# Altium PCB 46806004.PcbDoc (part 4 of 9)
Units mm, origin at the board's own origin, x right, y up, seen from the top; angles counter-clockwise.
Board outline 130 x 105 mm, 8 copper layers (Top Layer, P1-GND, L1-Signal, L2-Signal, L3-Signal, L4-Signal, P2-GND, Bottom Layer), stack 1.63 mm thick; 796 components, 496 nets, 2808 pads, 1195 vias.
Unrouted connection lines stored in the file: 1.
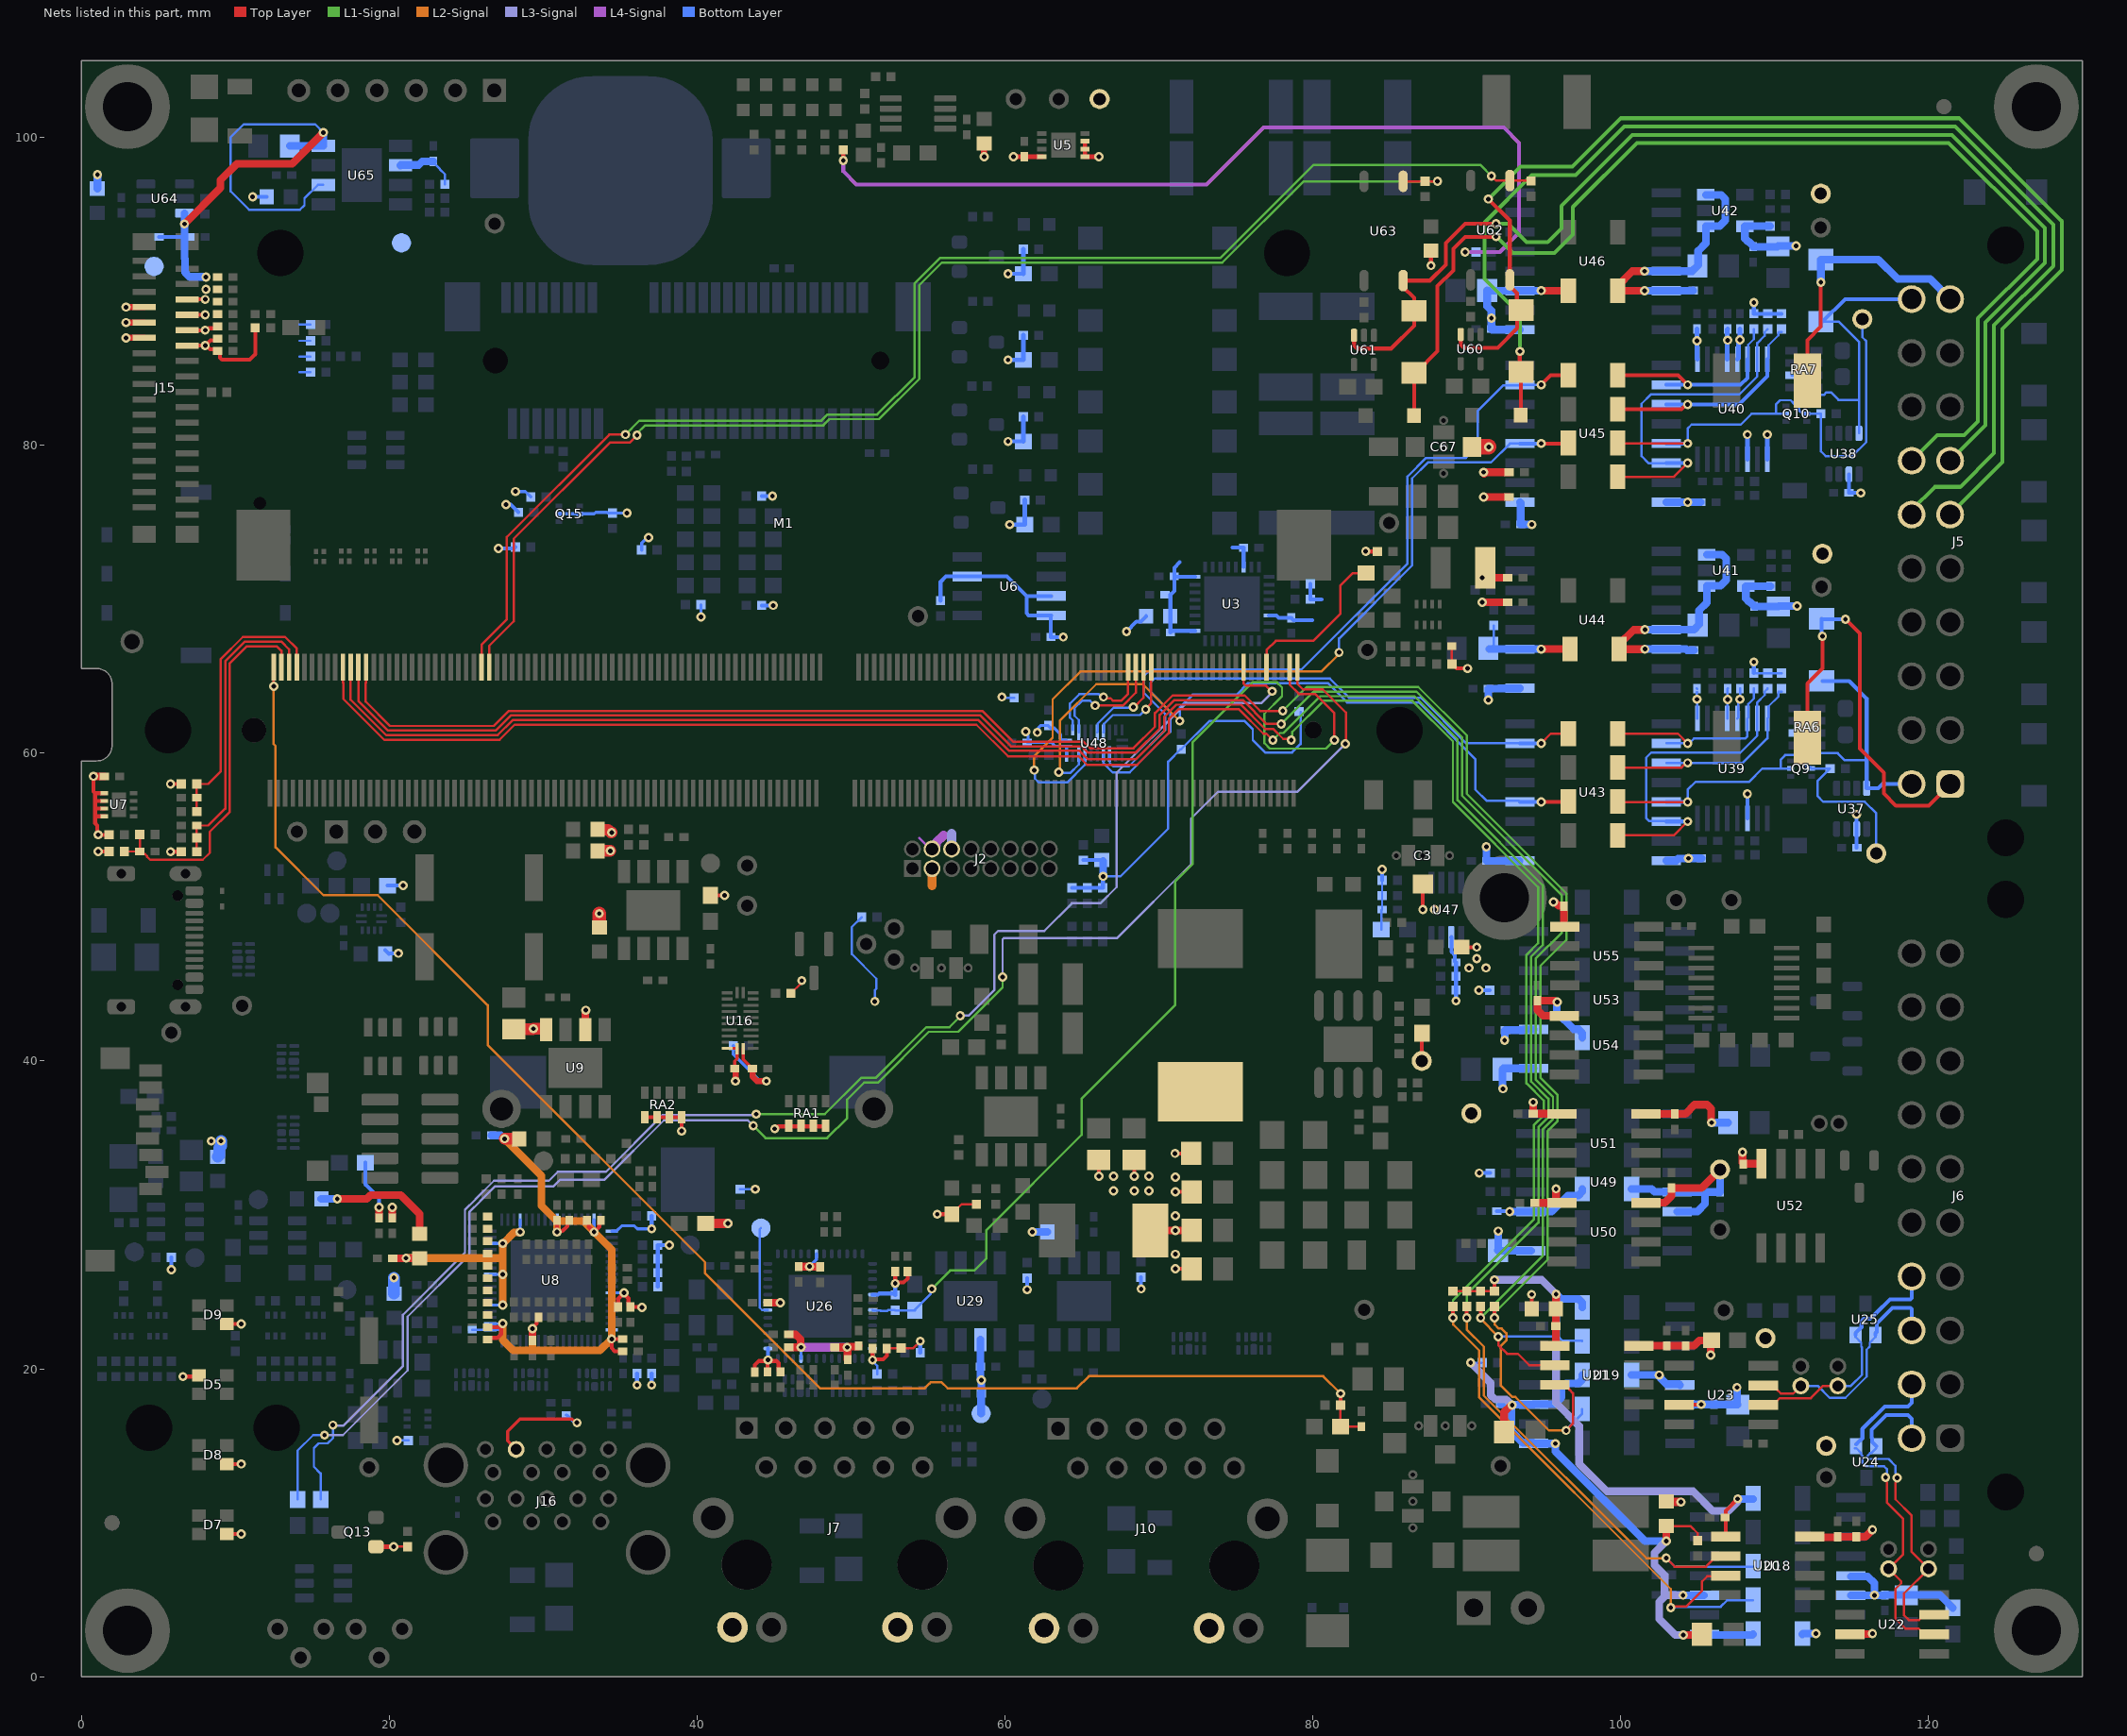
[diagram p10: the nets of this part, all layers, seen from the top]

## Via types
v1: diameter 0.6, hole 0.3, Top Layer to Bottom Layer, tented both sides, 1130 vias
v2: diameter 0.6, hole 0.3, Top Layer to Bottom Layer, 53 vias
v3: diameter 0.3, hole 0.3, Top Layer to Bottom Layer, 12 vias

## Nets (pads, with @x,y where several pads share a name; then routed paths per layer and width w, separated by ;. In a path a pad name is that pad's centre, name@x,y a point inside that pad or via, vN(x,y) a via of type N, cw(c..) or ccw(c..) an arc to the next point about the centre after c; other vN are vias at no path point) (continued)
1V8: C14.2 C16.2 C111.2 C135.2 C137.2 C140.2 C144.2 C147.2 C150.2 C153.2 C157.2 C160.2 C161.2 C162.2 C164.2 C215.2 C216.2 J2.6 L3.1 L4.2 L25.1 L29.1 L32.2 Q15.2 Q15.5 R4.1 R7.2 R56.2 R58.2 R61.2 R85.2 R115.2 R117.1 R120.2 R121.2 R133.1 R140.2 R147.2 R157.2 R183.2 R184.2 R215.1 R220.2 R221.2 R222.1 R224.2 R264.1 R265.1 R267.1 R269.1 R274.2 R275.2 R276.2 RA1.1 RA1.2 RA1.3 RA1.4 U5.1 U5.2 U5.3 U5.8 U7.5 U7.6 U7.7 U7.8 U16.24 U26.13 U26.19 U26.30 U26.41 U26.48 U47.2 U48.24 X2.1 | length 107.4
  Top Layer w0.15: R222.1@46.1,44.4 46.714,45.014 46.714,45.139 v1(46.8,45.225)
  Top Layer w0.156: C135.2@52.325,21.325 52.35,21.35 R221.2@53.25,21.35 54.05,21.35 v1(54.5,21.8) ; v1(52.871,25.547) v1@52.934,25.484
  Top Layer w0.2: U16.24@43,40.8 43,40.1 C111.2@43.6,39.5
  Top Layer w0.25: v1(0.8,58.5) 0.8,57.5 0.9,57.4 ; U7.8@1.5,55.9 0.9,55.9 ; U7.7@1.5,56.4 0.9,56.4 ; U7.6@1.5,56.9 0.9,56.9 ; U7.5@1.5,57.4 0.9,57.4 ; R7.2@1.8,54.7 v1(1.1,54.7) 1.033,54.767 1.033,55.313 0.9,55.446 0.9,55.9 ; v1(5.8,58) R56.2@6.5,58 ; C160.2@43.75,19.8 43.75,20.25 44.015,20.515 44.537,20.515 v1@44.59,20.567 ; C162.2@44.575,19.803 44.59,19.818 v1@44.59,20.567 ; C164.2@45.424,19.803 45.299,19.928 45.299,20.363 45.148,20.515 44.671,20.515 v1(44.604,20.582) v1@44.59,20.567 ; C144.2@51.4,21.325 51.402,21.323 51.402,20.584 v1(51.404,20.582) 51.452,20.629 52.079,20.629 52.325,20.875 C135.2@52.325,21.325 ; v1(51.55,43.875) v1@51.617,43.808 ; v1(52.871,25.547) v1@52.872,25.548 ; C153.2@52.874,26.318 C153.2@52.874,26.318 v1@52.872,25.548 ; C137.2@53.674,26.318 53.674,25.868 53.42,25.614 52.938,25.614 v1@52.872,25.548 ; v1@83.445,73.1 R133.1@84.2,73.1 ; v1(87.675,91.678) L32.2@87.675,92.643 ; L25.1@94.21,23.9 v1(94.21,24.838) ; 0.9,55.9 0.9,56.4 ; 0.9,56.4 0.9,56.9 ; 0.9,56.9 0.9,57.4
  Top Layer w0.3: v1(45.05,35.6) 45.131,35.6 45.281,35.75 47.55,35.75 48.3,35.75 RA1.4@48.35,35.8 ; v1(60.55,98.75) 61.45,98.75 U5.8@62.4,98.75 ; U5.3@65.2,99.75 U5.2@65.2,99.25 U5.1@65.2,98.75 v1(66.1,98.75)
  Top Layer w0.4: C111.2@43.6,39.5 43.6,39 43.9,38.7 v1(44.5,38.7) ; v1(58.65,98.75) L29.1@58.65,99.61
  Top Layer w0.5: v1(0.8,58.5) C16.2@1.5,58.5 ; C161.2@19.35,29.8 v1(19.35,30.5) ; C157.2@20.2,29.8 v1(20.2,30.5) ; C147.2@44.6,24.3 v1(45.4,24.3) ; C150.2@46.6,26.65 v1(47.3,26.65) 47.312,26.638 47.987,26.638 C140.2@48,26.625
  L3-Signal w0.15: 56.535,54.785 56.55,54.8
  L3-Signal w0.6: J2.6@56.535,53.775 56.535,54.785
  Bottom Layer w0.15: R58.2@50.7,49.35 50.05,48.7 50.05,46.95 51.65,45.35 51.65,44.698 51.55,44.598 v1(51.55,43.875) ; v1(59.8,63.65) 59.85,63.6 R274.2@60.6,63.6 ; v1(66.375,52) 67.5,52 70.6,55.1 70.6,59.45 71.4,60.25 R275.2@71.45,60.25 73.3,62.1 75.55,62.1 76.1,61.55 76.1,60.85 76.9,60.05 78.65,60.05 79.2,60.6 R276.2@79.2,62.669
  Bottom Layer w0.156: R220.2@42.8,31.675 v1(43.775,31.675) ; v1(51.404,20.582) 51.404,20.502 51.7,20.206 R267.1@51.7,19.672
  Bottom Layer w0.2: v1(28.2,77) 28.85,77 R264.1@29.2,76.65 ; Q15.5@31.025,75.55 Q15.2@32.375,75.55 33.322,75.55 33.422,75.65 34.15,75.65 34.2,75.6 R269.1@34.5,75.6 v1(35.45,75.6) ; R224.2@36.4,73.2 36.4,73.648 36.752,74 v1(36.85,74) ; v1(40.25,68.85) R85.2@40.25,69.65 ; R215.1@42.35,41 42.35,40.45 44.076,38.724 44.476,38.724 v1(44.5,38.7) ; U26.19@44.6,24.325 44.612,24.312 45.388,24.312 v1(45.4,24.3) ; v1(47.3,26.65) 47.75,27.1 U26.30@47.75,27.475 ; v1(62.1,61.35) 62.186,61.436 62.186,61.661 62.325,61.8 C215.2@62.8,61.8 62.8,61.775 62.95,61.625 63.2,61.625 63.6,61.225 63.6,60.95 63.7,60.85 U48.24@63.975,60.85
  Bottom Layer w0.25: v1(5.85,26.45) R61.2@5.85,27.25 ; R157.2@18.466,33.4 18.466,31.984 19.35,31.1 v1(19.35,30.5) ; R147.2@44.2,69.6 v1(44.95,69.6) ; R140.2@44.2,76.7 v1(44.9,76.7) ; v1@44.6,20.586 U26.13@44.6,21.325 ; v1@51.4,20.586 U26.48@51.4,21.325 ; U26.41@51.4,24.825 51.762,24.825 51.837,24.9 52.672,24.9 52.7,24.872 52.807,24.872 R121.2@52.875,24.803 v1@52.875,25.543 ; R265.1@54.5,21.05 v1(54.5,21.8) ; R120.2@64.35,51.25 R115.2@65.35,51.25 R117.1@66.35,51.25 66.362,51.262 66.362,51.988 v1(66.375,52) ; R4.1@65.1,53.05 66.29,53.05 L3.1@66.3,53.06 L3.1@66.35,53.01 ; v1(67.9,67.9) 68.54,68.54 68.825,68.54 69.16,68.875 L4.2@69.16,68.9 ; U47.2@88.975,48.025 U47.2@89,48.05 89,47.1 89.221,46.879 89.221,46.479 C216.2@89.3,46.4 R183.2@89.3,45.5 R184.2@89.3,44.62 v1@89.3,43.908
  Bottom Layer w0.3: L3.1@66.35,53.01 L3.1@66.375,52.985
  Bottom Layer w0.5: v1(66.375,52) L3.1@66.375,52.985
  other v1: 89.301,43.907 83.437,73.107
1V8_CAN: C119.1 C120.1 L25.2 R90.1 R91.2 R225.1 R226.1 R227.1 R228.1 U20.1 U21.1 | length 40.9
  Top Layer w0.15: R227.1@89.1,25.05 R225.1@90,25.05 R226.1@90.9,25.05 R228.1@91.8,25.05
  Top Layer w0.25: R228.1@91.8,25.05 v1(91.8,25.787) ; U20.1@106.819,9.065 106.819,10.271 106.78,10.31 106.829,10.359 106.829,10.789 v1(107.6,11.56)
  Top Layer w0.5: U21.1@95.72,21.505 95.788,21.573 C120.1@95.788,22.784 95.788,23.9 95.8,23.912 v1(95.8,24.85)
  L3-Signal w0.5: v1(91.8,25.787) 94.863,25.787 v1(95.8,24.85) 95.8,17.8 97.3,16.3 97.3,13.85 99.1,12.05 103.618,12.05 103.62,12.052 104.703,12.052 105.966,10.789 107.005,10.789 107.581,11.364 107.581,11.541 v1(107.6,11.56)
  Bottom Layer w0.5: v1(95.8,24.85) 95.827,24.85 96.127,24.55 97.25,24.55 97.5,24.3 R90.1@97.5,24 ; v1@107.61,11.55 R91.2@108.6,11.55
1V8_SW: C242.2 C247.2 C249.2 J15.23 J15.24 R200.2 R201.2 R203.2 R207.2 R208.2 R210.2 U65.6 X80.1 | length 15.8
  Top Layer w0.25: J15.23@6.881,86.478 v1(8.05,86.478) ; C249.2@8.85,86.928 8.734,86.813 8.384,86.813 v1(8.05,86.478) ; R210.2@11.3,87.628 11.3,85.919 10.934,85.553 9.148,85.553 9.001,85.699 9.001,86.003 8.876,86.128 C247.2@8.85,86.128 8.748,86.23 8.371,86.23 8.123,86.478 v1(8.05,86.478)
  Top Layer w0.4: v1(2.913,86.978) J15.24@4.081,86.978
  Bottom Layer w0.15: 14.175,84.742 R200.2@14.892,84.742 ; 14.175,85.767 R201.2@14.892,85.767 ; 14.175,86.792 R207.2@14.892,86.792 ; 14.175,87.842 R208.2@14.892,87.842 ; C242.2@22.9,98.35 23.3,97.95 23.3,97.925 23.625,97.6 R203.2@23.625,96.95
  Bottom Layer w0.5: U65.6@20.725,98.185 20.752,98.212 21.912,98.212 22.15,98.45 C242.2@22.875,98.45
1V8C: C9.2 C10.2 C11.2 C12.2 C13.2 C15.2 L4.1 R9.2 R10.2 R11.2 U3.1 U3.8 U3.14 U3.22 U6.3 U6.7 U6.8 | length 28.6
  Bottom Layer w0.25: R11.2@55.817,69.911 55.817,71.127 56.171,71.481 U6.3@57.556,71.481 60.131,71.481 61.401,70.211 ; U6.7@63.017,70.211 61.401,70.211 ; v1(63.786,67.546) C15.2@62.986,67.546 62.986,68.911 U6.8@63.017,68.941 61.548,68.941 61.401,69.088 61.401,70.211 ; 71.35,72.4 71,72.05 C9.2@71,71.5 ; U3.1@72.35,67.95 70.85,67.95 C11.2@70.75,67.85 70.75,70.3 71,70.55 C9.2@71,71.5 ; U3.8@72.35,71.45 71.05,71.45 C9.2@71,71.5 ; 74.775,73.35 C13.2@75.5,73.35 U3.14@75.5,72.1 ; U3.22@77.15,68.95 77.637,68.95 77.787,68.8 C10.2@78.6,68.8 78.6,68.765 78.725,68.64 79.956,68.64 ; R10.2@79.838,71 R9.2@79.838,70 80.563,70
2V5: C143.2 C146.2 C149.2 C152.2 C155.2 C165.2 R22.2 R127.2 U26.3 U26.9 U29.6 X52.1 | length 15.4
  Top Layer w0.5: C146.2@45.95,21.4 v1(46.75,21.4) 46.725,21.425 46.725,21.925 46.4,22.25 C143.2@45.95,22.25 ; C155.2@48.95,21.4 v1(49.75,21.4) ; C152.2@49.8,20.6 49.775,20.625 49.775,21.375 v1(49.75,21.4) ; C149.2@50.5,21.5 50.45,21.45 49.8,21.45 v1(49.75,21.4)
  Top Layer w0.6: R22.2@40.55,29.45 v1(42,29.45)
  L4-Signal w0.6: v1(46.75,21.4) v1(49.75,21.4)
  Bottom Layer w0.2: U26.9@46.75,20.675 v1(46.75,21.4) ; U26.3@49.75,20.675 v1(49.75,21.4)
  Bottom Layer w0.5: U29.6@58.4,21.9 58.4,19.36 58.465,19.295 R127.2@58.465,18.45 58.45,18.435 X52.1@58.45,17.1
  other v1: 58.465,19.268
3V2_AIN1: C183.1 C191.2 C194.1 C195.2 C197.2 C199.2 C203.2 R165.1 R168.2 R170.2 R172.2 U37.6 U39.3 U39.9 U39.12 U39.13 U41.5 U43.16 X61.1 | length 20.4
  Bottom Layer w0.15: C197.2@104.95,64.2 C197.2@104.975,64.175 ; U39.9@104.975,62.25 104.962,62.262 104.962,63.488 v1(104.95,63.5) 104.95,63.95 C197.2@104.975,63.975 ; U39.12@106.925,62.25 106.925,64.175 C195.2@106.95,64.2 ; U39.13@107.575,62.25 107.65,62.325 107.65,63.278 107.75,63.378 C199.2@107.75,64.2 ; R172.2@108.65,65.2 R170.2@109.55,65.2 R168.2@110.45,65.2
  Bottom Layer w0.25: U39.3@108.225,55.75 v1(108.225,57.35) ; R172.2@108.65,65.2 v1(108.65,65.928) ; C183.1@115.325,53.85 U37.6@115.325,55.073 v1(115.325,56.023)
  Bottom Layer w0.5: U43.16@102.95,53.018 103.6,53.018 103.731,53.149 104.381,53.149 v1(104.4,53.168) ; v1@104.402,53.166 C203.2@105.242,53.166 ; R165.1@109.747,70.852 U41.5@108.13,70.852 108.13,70.048 108.335,69.843 108.385,69.843 108.66,69.568 C194.1@108.66,69.543 108.66,69.518 110.235,69.518 110.282,69.565 v1(111.46,69.565)
  other v1: 106.946,63.482 107.75,63.5
3V2_AIN2: C184.1 C192.2 C193.1 C196.2 C198.2 C201.2 C204.2 R164.1 R169.2 R171.2 R173.2 U38.6 U40.1 U40.3 U40.9 U40.12 U40.13 U42.5 U45.16 X60.1 | length 21.9
  Bottom Layer w0.25: v1(108.65,89.278) R173.2@108.65,88.55 R171.2@109.55,88.55 R169.2@110.45,88.55 ; U38.6@114.825,78.126 C184.1@114.825,76.921 114.836,76.911 115.589,76.911 v1(115.6,76.9)
  Bottom Layer w0.3: C196.2@104.95,87.55 v1(104.95,86.8) 104.962,86.788 104.962,85.612 U40.9@104.975,85.6 ; U40.12@106.925,85.6 106.925,87.525 C198.2@106.95,87.55 ; U40.13@107.575,85.6 107.65,85.675 107.65,86.628 107.75,86.728 C201.2@107.75,87.55 ; U40.3@108.225,79.1 v1(108.225,80.7) ; U40.1@109.525,79.1 v1(109.525,80.7)
  Bottom Layer w0.5: U45.16@102.969,76.309 v1@104.349,76.309 ; v1(104.35,76.31) 104.355,76.305 105.195,76.305 C204.2@105.2,76.3 ; R164.1@109.7,94.25 109.694,94.243 108.076,94.243 U42.5@108.07,94.237 108.07,93.433 108.275,93.228 108.325,93.228 108.6,92.953 C193.1@108.6,92.903 110.175,92.903 C192.2@110.2,92.928 110.222,92.95 v1(111.4,92.95)
  other v1: 106.946,86.832 107.75,86.85
3V3: C62.2 C63.2 C83.2 C86.2 C88.2 C89.2 C91.2 C114.2 C207.2 C208.2 C209.2 C213.2 C219.1 C220.1 C228.1 C229.1 C251.2 J2.3 J7.11 J7.13 J10.11 J10.13 J15.25 L5.1 L6.1 L11.2 L26.1 L27.1 L28.1 L31.1 L33.1 Q13.1 R12.1 R13.1 R14.2 R15.2 R16.2 R17.1 R18.1 R36.2 R53.2 R98.1 R99.1 R100.1 R101.1 R102.1 R103.1 R104.1 R105.1 R180.2 R181.2 R182.1 R249.2 R263.2 R270.1 R271.1 RA2.1 RA2.2 RA2.3 RA2.4 U8.28 U16.22 U16.23 U43.1 U45.1 U48.22 U48.23 U50.1 U51.1 U54.1 U55.1 X17.1 | length 84
  Top Layer w0.15: v1(20.3,8.45) R263.2@21.2,8.45 ; C114.2@42.45,39.5 C114.2@42.5,39.45 ; U16.23@42.575,40.825 U16.23@42.6,40.8 ; C83.2@89.023,66.95 89.023,65.821 R36.2@89.048,65.796
  Top Layer w0.2: U16.22@41.95,40.825 U16.23@42.575,40.825 ; C114.2@42.45,39.5 42.45,40 42.6,40.15 U16.23@42.6,40.8
  Top Layer w0.25: v1(5.8,53.6) R53.2@6.5,53.6 ; J15.25@6.881,87.478 v1(8.05,87.478) 8.144,87.478 8.269,87.603 8.725,87.603 C251.2@8.85,87.728 ; C63.2@34.873,24.025 34.873,24.556 v1(35.265,24.947) 35.265,24.853 35.548,24.569 35.548,24.15 C62.2@35.673,24.025 ; C62.2@35.679,24.03 35.697,24.012 36.405,24.012 v1(36.417,24) ; RA2.1@36.6,36.35 RA2.2@37.4,36.35 RA2.3@38.2,36.35 RA2.4@39,36.35 v1(39,35.45) ; R36.2@89.051,65.799 89.35,65.5 v1(90.05,65.5)
  Top Layer w0.3: Q13.1@19.15,8.45 v1(20.3,8.45)
  Top Layer w0.4: v1(42.5,38.7) C114.2@42.5,39.45
  Top Layer w0.5: v1(16.63,31.05) 18.554,31.05 18.803,31.3 20.75,31.3 21.983,30.067 L5.1@21.983,28.774 ; v1(91,69.8) C88.2@92.65,69.8 ; v1(91,71.4) C86.2@92.65,71.4 ; v1(91.1,76.65) C89.2@92.75,76.65 ; v1(91.1,78.25) C91.2@92.75,78.25 ; v1(94.322,37.322) C220.1@94.322,36.585 96.175,36.585 U51.1@96.191,36.568 ; C219.1@94.422,30.785 96.184,30.785 U50.1@96.191,30.792 95.992,30.792 95.8,30.985 v1(95.8,31.7) ; v1(95.639,50.339) 95.658,50.32 95.739,50.32 95.96,50.1 C228.1@96.3,50.1 ; v1(95.883,43.825) 95.788,43.825 95.689,43.924 C229.1@94.594,43.924 94.594,43.306 94.966,42.934 U54.1@96.347,42.934 ; C228.1@96.3,50.05 C228.1@96.3,50.1 ; U55.1@96.37,48.734 96.3,48.804 C228.1@96.3,50.1
  Top Layer w0.75: L28.1@33.54,53.654 v1(34.365,53.654) ; L27.1@33.54,55.054 33.575,55.019 34.222,55.019 34.391,54.85 v1(34.45,54.85)
  Top Layer w0.9: L6.1@33.65,48.68 v1(33.65,49.58)
  L2-Signal w0.2: 55.265,51.385 55.3,51.35
  L2-Signal w0.6: 55.265,51.385 J2.3@55.265,52.505
  Bottom Layer w0.15: v1(20.5,15.35) R16.2@21.25,15.35 ; R182.1@84.45,48.545 84.45,49.795 C209.2@84.5,49.845 R181.2@84.5,50.745 R180.2@84.5,51.745
  Bottom Layer w0.2: U8.28@34.459,24.947 v1(35.265,24.947) ; v1(61.35,61.4) 61.35,61.3 61.5,61.15 61.5,60.75 C213.2@61.45,60.7 63.025,60.7 63.275,60.45 U48.23@63.975,60.45 64,60.425 U48.22@64,59.8
  Bottom Layer w0.25: v1(11.135,96.15) L33.1@12.035,96.15 ; v1(27.1,73.3) 28.1,73.3 R270.1@28.2,73.4 ; v1(27.6,76.15) 27.9,76.15 R271.1@28.4,75.65 ; v1(36.1,18.95) R14.2@36.1,19.7 ; v1(37.05,18.95) R15.2@37.05,19.7 ; R17.1@37.45,25.35 R18.1@37.45,26.25 R13.1@37.45,27.15 R12.1@37.45,28.05 v1(38.2,28.05) ; v1(60.2,80.25) R103.1@61.197,80.249 ; v1(60.2,85.55) R104.1@61.197,85.549 ; v1(60.2,91.15) 61.196,91.15 R105.1@61.197,91.149 ; v1(60.3,74.85) R102.1@61.296,74.85 ; R180.2@84.5,51.745 v1(84.5,52.45)
  Bottom Layer w0.3: R103.1@61.197,80.249 R99.1@61.197,81.849 ; R104.1@61.197,85.549 R100.1@61.197,87.149 ; R105.1@61.197,91.149 R101.1@61.197,92.749 ; R102.1@61.297,74.849 R98.1@61.297,76.449
  Bottom Layer w0.5: L31.1@15.59,31.05 v1(16.63,31.05) ; v1(61.775,28.9) 62.75,28.9 L26.1@62.76,28.91 ; v1(91.267,53.917) 91.284,53.901 91.284,53.016 C207.2@91.3,53 U43.1@93.432,53 ; U45.1@93.45,76.308 93.5,76.258 C208.2@93.5,74.853 v1@94.212,74.853 ; v1(95.883,43.825) 95.883,43.798 95.85,43.765 95.85,43.168 96.95,42.068 97.25,42.068 97.5,41.818 R249.2@97.5,41.518
  other v1: 94.213,74.854
5V: C3.1 C61.2 C67.1 C87.1 C92.2 C93.2 C94.2 C95.2 C96.2 C98.2 C99.2 C210.1 C211.1 C212.2 C214.2 C217.2 C218.1 C226.2 C227.1 D5.1 D7.1 D8.1 D9.1 J2.4 L13.2 L14.2 L15.1 L16.1 L24.1 L34.1 L40.1 R39.2 R44.2 R50.2 R51.2 R59.2 R125.2 R126.2 R138.2 R177.2 R179.2 R187.2 R191.2 R211.2 R243.2 R255.1 R261.1 U8.18 U9.2 U9.4 U44.1 U44.3 U46.1 U46.3 U49.1 U49.3 U53.1 U53.3 X18.1 | length 133.2
  Top Layer w0.15: C87.1@56.55,30.05 57.2,30.7 R39.2@58.15,30.7
  Top Layer w0.25: v1(1.1,53.613) R51.2@1.8,53.613 ; v1(6.6,19.5) 7.578,19.5 D5.1@7.648,19.571 ; D7.1@9.45,9.275 v1(10.394,9.275) ; D8.1@9.45,13.825 v1(10.394,13.825) ; D9.1@9.45,22.925 v1(10.394,22.925) ; R138.2@40.865,50.77 v1(41.795,50.77) ; v1(49.502,98.5) R50.2@49.502,99.2 ; v1(55.6,30.05) C87.1@56.55,30.05 ; v1(66.1,32.525) C95.2@66.1,33.575 ; v1(68.4,32.525) C94.2@68.4,33.575 ; v1(71.05,34) C92.2@72.1,34 ; v1(71.075,26.5) C96.2@72.125,26.5 ; v1(71.075,31.5) C99.2@72.125,31.5 ; R44.2@86.875,41.803 R44.2@86.9,41.828 ; X18.1@87.075,40.007 R44.2@87.075,41.775 ; v1(87.15,49.85) C3.1@87.15,51.5 ; C93.2@89.675,47.4 v1(90.65,47.4)
  Top Layer w0.5: U9.2@32.735,42.05 32.75,42.065 32.75,43.285 v1(32.765,43.3) ; L13.2@69.45,29 v1(71.075,29) C98.2@72.125,29 ; v1(94.831,66.759) 96.696,66.759 R255.1@96.7,66.763 ; v1@94.834,90.049 R261.1@96.6,90.049
  Top Layer w0.55: L24.1@102.952,11.352 v1(103.91,11.352)
  Top Layer w0.75: C61.2@28.1,42.075 v1@29.34,42.075 ; v1(29.365,42.1) 30.145,42.1 U9.4@30.195,42.05
  Top Layer w1: C67.1@90.35,79.9 v1(91.425,79.9)
  L4-Signal w0.15: 54.42,54.503 55.148,53.775 J2.4@55.265,53.775
  L4-Signal w0.25: v1(49.502,98.5) 49.502,97.798 50.35,96.95 73.1,96.95 76.8,100.65 92.4,100.65 93.4,99.65 93.4,93.8 92.152,92.552 v1(89.887,92.552)
  L4-Signal w0.6: J2.4@55.265,53.775 55.535,54.045 55.535,54.189 56.011,54.665
  Bottom Layer w0.15: C212.2@91.464,66.758 91.75,67.044 R177.2@91.75,68.3
  Bottom Layer w0.2: U8.18@34.459,28.947 34.761,28.947 35.113,29.3 35.928,29.3 36.128,29.1 v1(37.05,29.1)
  Bottom Layer w0.25: L16.1@19.74,47.2 19.99,46.95 20.04,47 v1(20.6,47) ; R59.2@19.9,51.4 v1(20.9,51.4) ; v1(37.05,29.1) R211.2@37.05,29.95 ; v1(61.45,25.15) R125.2@61.45,25.9 ; R126.2@68.825,25.95 68.838,25.938 68.838,25.212 v1(68.85,25.2) ; v1(89.887,92.552) R179.2@90.6,92.553 ; v1@90.788,44.607 R191.2@91.5,44.607 ; v1@90.81,32.723 R187.2@91.522,32.723 ; C218.1@91.95,30.25 92.758,30.25 v1(92.791,30.217)
  Bottom Layer w0.5: L34.1@1.05,96.68 v1(1.05,97.59) ; v1(91.4,63.45) C210.1@91.4,64.2 ; C212.2@91.464,66.758 U44.3@93.45,66.758 v1(94.831,66.759) ; C210.1@91.522,64.2 92.1,64.2 92.109,64.209 93.441,64.209 U44.1@93.45,64.218 ; v1(91.599,88.266) 91.599,88.751 91.325,89.025 C214.2@91.325,90.053 91.33,90.048 U46.3@93.45,90.048 ; v1@91.6,88.265 C211.1@91.6,87.553 91.645,87.508 U46.1@93.45,87.508 ; C217.2@92.025,27.7 C217.2@92.047,27.678 ; v1(92.05,28.95) 92.047,28.947 C217.2@92.047,27.678 ; v1(92.35,38.2) 92.325,38.225 C226.2@92.325,39.468 92.38,39.523 U53.1@94.35,39.523 ; v1(92.46,41.343) 92.48,41.363 92.48,41.987 C227.1@92.5,42.007 93.644,42.007 93.7,42.063 U53.3@94.35,42.063 ; v1@92.792,30.218 U49.3@94.172,30.218 95.518,30.218 96.57,31.27 97.25,31.27 97.5,31.52 R243.2@97.5,31.7 ; U46.3@93.452,90.05 v1@94.829,90.05 ; U49.1@94.172,27.678 C217.2@92.047,27.678
  Bottom Layer w0.75: L15.1@8.85,33.79 8.88,33.79 8.965,33.875 8.965,34.365 9.082,34.482 v1(9.082,34.8) ; L40.1@20.311,24.89 v1(20.311,25.93)
  other v1: 71.075,27.45 71.075,29.95 67.05,31.575 68.4,31.575 69.35,31.575 71.075,32.45 67.05,32.525 69.35,32.525 90.809,32.721 8.441,34.801 90.787,44.605 90.15,46.05 91.25,46.05 90.65,46.65 87.9,49.85 94.831,90.052
5V_485: C221.1 C222.1 C223.1 C224.2 C225.1 R243.1 U49.13 U49.14 U50.8 U51.8 U52.8 X69.1 | length 24.6
  Top Layer w0.25: C222.1@103.517,36.568 C222.1@103.522,36.563
  Top Layer w0.5: U50.8@101.652,30.792 102.859,30.792 103.288,31.221 103.288,31.738 C221.1@103.3,31.75 105.248,31.75 X69.1@106.448,32.95 ; U51.8@101.652,36.568 C222.1@103.517,36.568 ; C222.1@103.522,36.563 104.205,36.563 104.81,37.168 105.607,37.168 105.881,36.894 105.881,36.019 v1(105.9,36) ; v1(107.913,34.078) 107.913,33.398 107.981,33.33 U52.8@109.145,33.33
  Bottom Layer w0.5: R243.1@100.7,31.7 102,31.7 102.2,31.5 103.66,31.5 U49.13@103.672,31.488 105.474,31.488 ; U49.14@103.672,30.218 103.68,30.225 104.975,30.225 105.474,30.724 105.474,31.488 ; v1(105.9,36) C224.2@106.975,36 ; X69.1@106.448,32.95 C223.1@106.45,31.488 105.474,31.488
5V_AIN1: C200.2 C205.1 R255.2 U41.1 U41.3 U44.13 U44.14 | length 17.8
  Top Layer w0.5: v1(101.569,66.757) 99.906,66.757 R255.2@99.9,66.763 99.9,67.063 100.845,68.008 101.55,68.008 v1(101.569,68.027)
  Bottom Layer w0.5: v1@101.57,66.758 U44.14@102.95,66.758 104.24,66.758 104.307,66.69 C205.1@104.757,66.69 ; v1(101.569,68.027) U44.13@102.949,68.027 ; U44.13@102.95,68.028 104.77,68.028 105.094,68.353 105.094,69.272 105.59,69.767 U41.1@105.59,70.852 105.59,70.877 106.497,70.877 106.86,71.24 106.86,72.64 106.591,72.909 U41.3@105.59,72.909
5V_AIN2: C202.2 C206.1 R261.2 U42.1 U42.3 U46.13 U46.14 | length 17.9
  Top Layer w0.5: v1(101.55,90.046) 99.807,90.046 R261.2@99.8,90.053 99.8,90.353 100.763,91.316 v1(101.55,91.316)
  Bottom Layer w0.5: v1@101.551,90.047 U46.14@102.931,90.047 ; v1@101.551,91.317 U46.13@102.931,91.317 ; U46.14@102.95,90.048 102.952,90.05 104.697,90.05 C206.1@104.7,90.053 ; U46.13@102.95,91.318 104.64,91.318 105.035,91.713 105.035,92.632 105.53,93.127 U42.1@105.53,94.237 106.437,94.237 106.8,94.6 106.8,96 106.531,96.269 U42.3@105.53,96.269
5V_CAN: C115.2 C116.2 C117.1 C118.1 L24.2 R86.2 R87.2 R233.2 R237.1 U18.1 U18.3 U19.1 U19.3 | length 49.3
  Top Layer w0.15: L24.2@102.95,9.77 104.55,9.77 105,9.32 R86.2@105,8.81
  Top Layer w0.25: L24.2@102.95,9.77 L24.2@102.952,9.768
  Top Layer w0.5: C116.2@92.425,15.9 92.425,17.175 92.881,17.631 92.931,17.631 v1(92.95,17.65) ; v1(102.952,8.81) L24.2@102.952,9.768 ; v1(104.069,2.714) 105.271,2.714 C115.2@105.275,2.71
  L3-Signal w0.5: v1(90.25,20.4) 91.55,19.1 91.55,18.3 91.843,18.007 92.566,18.007 92.923,17.65 v1(92.95,17.65) ; v1(102.952,8.81) 102.2,8.058 102.2,7.25 102.85,6.6 102.85,5.2 ; v1@104.042,2.714 103.536,2.714 102.5,3.75 102.5,4.85 102.85,5.2 ; v1(104.05,5.3) 104.031,5.281 102.931,5.281 102.85,5.2
  Bottom Layer w0.15: v1(90.25,20.4) R87.2@91,20.4
  Bottom Layer w0.5: C118.1@92.2,17.7 92.873,17.7 92.923,17.65 v1(92.95,17.65) ; R237.1@97.5,19.6 97.5,19.3 97.25,19.05 96.45,19.05 96.15,18.75 96.15,18.15 95.7,17.7 94.355,17.7 U19.3@94.35,17.695 94.324,17.669 92.969,17.669 v1(92.95,17.65) ; v1(102.952,8.81) 101.59,8.81 95.75,14.65 v1(95.75,15.15) 95.747,15.152 94.353,15.152 94.3,15.205 93.65,15.205 92.903,15.952 92.903,17.576 92.95,17.623 v1(92.95,17.65) ; C117.1@103.3,5.32 103.31,5.31 104.04,5.31 v1(104.05,5.3) 104.052,5.298 105.392,5.298 U18.3@105.395,5.3 ; v1(104.069,2.714) 108.555,2.715 R233.2@108.6,2.76
5V_CAN1: C121.1 C124.2 C125.2 C129.1 R92.2 R233.1 U18.13 U18.14 U20.8 U22.3 X30.1 | length 16.1
  Top Layer w0.5: U20.8@112.28,9.065 114.094,9.065 C129.1@114.1,9.06 ; C129.1@114.1,9.1 115.9,9.1 v1(116.35,9.55) ; U22.3@114.918,2.738 114.96,2.78 116.33,2.78 v1(116.35,2.8)
  Bottom Layer w0.5: R233.1@111.8,2.76 111.84,2.8 v1(112.675,2.8) ; U18.13@114.95,6.525 114.96,6.515 116.041,6.515 116.478,6.078 v1(116.478,5.3) ; U18.14@114.955,5.3 114.958,5.298 116.475,5.298 v1(116.478,5.3) ; C121.1@117.15,5.3 v1(116.478,5.3) ; C121.1@117.15,5.315 118.335,5.315 120.728,5.315 R92.2@121.567,4.476
5V_CAN2: C122.1 C123.2 C126.2 C130.1 R93.2 R237.2 U19.13 U19.14 U21.8 U23.3 X31.1 | length 15.7
  Top Layer w0.25: U23.3@103.8,17.66 103.818,17.678 105.213,17.678 v1(105.231,17.696)
  Top Layer w0.5: U21.8@101.181,21.505 102.995,21.505 C130.1@103,21.5 104.767,21.5 105.117,21.85 105.888,21.85 R93.2@105.9,21.862 105.85,21.812 v1(105.85,20.9)
  Bottom Layer w0.5: R237.2@100.7,19.6 102.497,19.6 v1(102.498,19.599) ; v1@102.5,19.6 102.5,19.57 102.565,19.505 102.565,19.422 102.972,19.015 103.783,19.015 U19.13@103.85,18.948 ; U19.14@103.85,17.695 v1(105.231,17.696) ; v1(105.231,17.696) C126.2@107.579,17.696 ; v1(107.55,18.8) 107.55,17.725 C126.2@107.579,17.696 ; C126.2@107.6,17.675 C126.2@107.579,17.696
+V5_SW: C240.2 C243.2 C244.2 C246.2 C248.2 C250.2 C252.2 J15.26 J15.27 J15.28 J15.29 U64.6 U65.2 U65.4 X81.1 | length 44
  Top Layer w0.25: J15.27@6.881,88.478 v1(8.05,88.478) ; J15.29@6.881,89.478 v1(8.05,89.478)
  Top Layer w0.4: v1(2.913,87.978) J15.26@4.081,87.978 ; v1(2.913,88.978) J15.28@4.081,88.978
  Top Layer w0.5: v1(6.7,94.378) 9.05,96.728 9.05,97.233 10.117,98.3 13.695,98.3 v1(15.72,100.325)
  Bottom Layer w0.15: v1(15.72,100.325) 15.195,100.85 10.55,100.85 9.7,100 9.7,96.5 10.9,95.3 14.2,95.3 14.5,95.6 14.5,96.041 15.373,96.915 U65.2@15.725,96.915
  Bottom Layer w0.25: C244.2@5.05,93.528 6.7,93.528 ; U64.6@6.7,95.073 U64.6@6.705,95.078
  Bottom Layer w0.5: U64.6@6.7,95.073 v1(6.7,94.378) 6.7,93.528 6.7,92.15 6.735,92.115 6.735,91.24 7.027,90.947 8.08,90.947 v1(8.1,90.928) ; C240.2@13.55,99.45 U65.4@15.72,99.45 ; v1(15.72,100.325) U65.4@15.72,99.45 ; U65.4@15.725,99.455 U65.4@15.72,99.45
  other v1: 8.1,90.128
ADC.ADC1: C97.1 M1.2 R48.1 R49.2 | length 102
  Top Layer w0.15: v1(12.5,64.353) M1.2@12.5,65.6 ; R49.2@81.8,17.5 R48.1@81.8,16.25 C97.1@83.15,16.25
  Top Layer w0.25: R49.2@81.8,17.65 v1(81.8,18.4)
  L2-Signal w0.15: v1(12.5,64.353) 12.5,60.592 12.625,60.467 12.625,53.883 15.733,50.775 19.253,50.775 26.4,43.628 26.4,41.05 40.525,26.925 40.525,26.21 47.993,18.742 54.792,18.742 55.1,19.05 55.108,19.05 55.183,19.125 55.892,19.125 56.275,18.742 64.667,18.742 65.45,19.525 80.675,19.525 v1(81.8,18.4) ; v1@81.725,18.325 v1@81.8,18.25
ADC.ADC2: C100.1 M1.4 R51.1 R52.2 | length 24.9
  Top Layer w0.15: R51.1@2.8,53.613 C100.1@3.8,53.613 ; R52.2@3.8,54.713 C100.1@3.8,53.613 ; M1.4@13,65.6 13,66.65 12.7,66.95 10.75,66.95 9.65,65.85 9.65,56.2 8.35,54.9 8.35,53.532 7.893,53.075 4.47,53.075 4.275,53.27 4.275,53.311 4.148,53.438 3.975,53.438 C100.1@3.8,53.613
ADC.ADC3: C101.1 M1.6 R53.1 R54.2 | length 19.6
  Top Layer w0.15: R53.1@7.5,53.6 R54.2@7.5,54.5 C101.1@7.5,55.3 8.25,55.3 9.35,56.4 9.35,65.976 10.624,67.25 12.993,67.25 13.5,66.743 M1.6@13.5,65.6
ADC.ADC4: C103.1 M1.8 R56.1 R57.2 | length 18
  Top Layer w0.15: R57.2@7.5,56.2 C103.1@7.5,57.1 R56.1@7.5,58 8.25,58 9.05,58.8 9.05,66.1 10.5,67.55 13.239,67.55 14,66.789 M1.8@14,65.6
AIN1+: D24.1 J5.2 RA6.2 U37.4 | length 18.1
  Bottom Layer w0.15: RA6.2@111.3,61.3 111.85,61.3 112.1,61.05 112.1,60.3 112.4,60 114.095,60 114.561,59.534 115.975,59.534
  Bottom Layer w0.25: D24.1@113.1,64.685 114.843,64.685 115.975,63.553 115.975,59.534 U37.4@115.975,57.727 116.727,57.727 117,58 J5.2@118.9,58
AIN1-: D24.2 J5.1 PTC5.1 | length 27.3
  Top Layer w0.25: PTC5.1@112.116,61 112.116,64.516 113.1,65.5 v1(113.1,67.6) ; v1(114.6,68.7) 115.531,67.769 115.531,60.29 117.1,58.721 117.1,57.376 117.876,56.6 120,56.6 J5.1@121.4,58
  Bottom Layer w0.25: v1(113.1,67.6) 113.054,67.646 D24.2@113.054,68.733 113.087,68.7 v1(114.6,68.7)
AIN1_DRDY_3V3: R253.1 U43.7 U48.16 | length 39.3
  Top Layer w0.15: v1(94.831,60.639) 95.455,61.263 R253.1@96.6,61.263
  Bottom Layer w0.15: U48.16@66.4,59.95 66.4,59.35 67,58.75 68.1,58.75 70.75,61.4 70.75,62.7 69.45,64 69.45,64.576 69.724,64.85 81.1,64.85 82.35,63.6 87,63.6 89.962,60.638 U43.7@93.45,60.638
  Bottom Layer w0.25: U43.7@93.45,60.638 v1@94.83,60.638
AIN1_DRDY_ISO: R172.1 R253.2 U39.14 U43.10 | length 13.5
  Top Layer w0.15: R253.2@99.8,61.263 103.727,61.263 v1(104.35,60.64)
  Bottom Layer w0.15: U43.10@102.969,60.639 v1@104.349,60.639 ; v1(104.35,60.64) 104.445,60.64 104.755,60.95 108.079,60.95 108.225,61.096 U39.14@108.225,62.25 108.284,62.309 108.284,63.184 108.65,63.55 R172.1@108.65,64.2
AIN1_MODE_3V3: R254.1 U43.4 U48.20 | length 46.5
  Top Layer w0.25: v1(94.831,56.829) 96.566,56.829 R254.1@96.6,56.863
  L2-Signal w0.15: v1(63.491,58.767) 63.564,58.84 63.564,62.114 65.937,64.487 68.963,64.487 v1(71.358,62.092)
  Bottom Layer w0.15: v1(63.491,58.767) 63.544,58.714 64.239,58.714 64.8,59.274 U48.20@64.8,59.95 ; v1(71.358,62.092) 71.358,62.958 72.2,63.8 75.05,63.8 75.8,64.55 80.976,64.55 82.226,63.3 86.876,63.3 90.55,59.626 90.55,57.65 91.3,56.9 93.378,56.9 U43.4@93.45,56.828
  Bottom Layer w0.25: U43.4@93.45,56.828 v1@94.83,56.828
AIN1_MODE_ISO: Q9.2 Q9.5 R175.2 R254.2 U43.13 X62.1 | length 27.3
  Top Layer w0.15: R254.2@99.8,56.863 99.833,56.83 v1(104.35,56.83)
  Bottom Layer w0.15: v1(104.35,56.83) 104.35,57.624 104.876,58.15 108.352,58.15 109.202,59 110.415,59 ; Q9.2@111.05,59 110.415,59 ; X62.1@116.6,53.5 116.6,56.1 115.85,56.85 113.15,56.85 112.776,57.224 112.776,58.176 R175.2@113.6,59 Q9.5@112.4,59 112.325,59.075 112.15,59.075 112.1,59.125 112.082,59.125 111.725,59.482 111.725,59.518 111.368,59.875 110.684,59.875 110.4,59.591 110.4,59.015 110.415,59
  Bottom Layer w0.25: U43.13@102.969,56.829 v1@104.349,56.829
AIN1_SCL_ISO: R168.1 R251.2 U39.16 U43.11 | length 15.4
  Top Layer w0.15: R251.2@99.8,59.063 103.948,59.063 104.255,59.37 v1(104.35,59.37)
  Bottom Layer w0.15: U43.11@102.969,59.369 v1@104.349,59.369 ; v1(104.35,59.37) 107.927,59.37 109.525,60.968 U39.16@109.525,62.25 109.6,62.325 109.6,63.039 110.241,63.68 110.241,63.975 110.266,64 R168.1@110.45,64
AIN1_SDA_ISO: R170.1 R252.2 U39.15 U43.14 | length 22.8
  Top Layer w0.15: R252.2@99.8,54.663 103.453,54.663 v1(104.35,55.56)
  Bottom Layer w0.15: U43.14@102.95,55.558 102.921,55.587 101.863,55.587 101.65,55.8 101.65,59.7 101.989,60.039 107.774,60.039 108.875,61.141 U39.15@108.875,62.25 108.875,63.296 109.355,63.776 109.355,64.005 R170.1@109.55,64.2
  Bottom Layer w0.25: U43.14@102.969,55.559 v1@104.349,55.559
AIN2+: D25.1 J5.20 RA7.2 U38.4 | length 21.2
  Bottom Layer w0.15: RA7.2@111.1,84.55 111.8,84.55 111.9,84.45 111.9,83.42 112.086,83.234 112.21,83.234 112.251,83.275 113.193,83.275 113.359,83.44 113.66,83.44 114.15,82.95 115.475,82.95 ; D25.1@113,88.038 113.12,88.038 114.162,88.038 115.475,86.725 115.475,82.95 ; U38.4@115.475,80.78 115.475,82.95
  Bottom Layer w0.25: D25.1@113.12,88.038 114.582,89.5 J5.20@118.9,89.5
AIN2-: D25.2 J5.19 PTC6.1 | length 17.7
  Top Layer w0.25: PTC6.1@112.116,84.2 112.116,86.816 113,87.7 v1(113,90.6)
  Bottom Layer w0.5: v1(113,90.6) D25.2@113,92.068 116.732,92.068 118,90.8 120.1,90.8 J5.19@121.4,89.5
AIN2_DRDY_3V3: R259.1 U45.7 U48.15 | length 49.7
  Top Layer w0.25: v1(94.831,83.929) 95.455,84.553 R259.1@96.6,84.553
  Bottom Layer w0.15: U48.15@66.8,60 66.8,59.55 66.809,59.541 66.809,59.365 67.024,59.15 68.05,59.15 70.4,61.5 70.4,62.55 69,63.95 69,64.974 69.476,65.45 79.276,65.45 86.15,72.324 86.15,77.974 87.36,79.184 89.934,79.184 90.7,79.95 90.7,82.228 92.358,83.886 93.408,83.886 U45.7@93.45,83.928 93.451,83.929 v1(94.831,83.929)
AIN2_DRDY_ISO: R173.1 R259.2 U40.14 U45.10 | length 13.6
  Top Layer w0.25: R259.2@99.8,84.553 103.727,84.553 v1(104.35,83.93)
  Bottom Layer w0.15: U40.14@108.225,85.6 108.284,85.659 108.284,86.534 108.65,86.9 R173.1@108.65,87.55
  Bottom Layer w0.25: U45.10@102.969,83.929 v1@104.349,83.929 ; v1(104.35,83.93) 107.78,83.93 108.225,84.375 U40.14@108.225,85.6
AIN2_MODE_3V3: R260.1 U45.4 U48.19 | length 54.5
  Top Layer w0.25: v1(94.831,80.119) 96.566,80.119 R260.1@96.6,80.153
  L2-Signal w0.15: v1(61.9,58.9) 61.9,59.8 63.1,61 63.1,63.5 64.9,65.3 80.55,65.3 81.7,66.45 v1(81.7,66.544)
  Bottom Layer w0.15: v1(61.9,58.9) 61.95,58.85 61.95,58.35 62.2,58.1 64.05,58.1 65.2,59.25 U48.19@65.2,59.95 ; v1(81.7,66.544) 81.7,67.45 86.45,72.2 86.45,77.85 87.484,78.884 91.566,78.884 92.8,80.118 U45.4@93.45,80.118
  Bottom Layer w0.25: U45.4@93.45,80.118 v1(94.831,80.119)
AIN2_MODE_ISO: Q10.2 Q10.5 R174.2 R260.2 U45.13 X63.1 | length 31.8
  Top Layer w0.15: R260.2@99.8,80.153 99.833,80.12 v1(104.35,80.12)
  Bottom Layer w0.15: v1(104.35,80.12) 104.35,81.097 104.603,81.35 107.8,81.35 108.503,82.053 110.078,82.053 ; Q10.2@110.725,82.053 110.078,82.053 ; X63.1@115.7,88.2 115.7,87.018 115.958,86.761 115.958,80.214 115.048,79.305 113.308,79.305 113,79.613 R174.2@113,82.053 Q10.5@112.075,82.053 111.792,82.053 111.597,82.248 111.597,82.356 111.175,82.778 111.175,82.796 111.043,82.928 110.345,82.928 110.078,82.661 110.078,82.053
  Bottom Layer w0.25: U45.13@102.969,80.119 v1@104.349,80.119
AIN2_SCL_ISO: R169.1 R257.2 U40.16 U45.11 | length 15.3
  Top Layer w0.25: R257.2@99.8,82.353 103.948,82.353 104.255,82.66 v1(104.35,82.66)
  Bottom Layer w0.15: U40.16@109.525,85.6 109.6,85.675 109.6,86.5 110.241,87.141 110.241,87.325 110.266,87.35 R169.1@110.45,87.35
  Bottom Layer w0.25: U45.11@102.969,82.659 v1@104.349,82.659 ; v1(104.35,82.66) 107.687,82.66 109.525,84.498 U40.16@109.525,85.6
AIN2_SDA_ISO: R171.1 R258.2 U40.15 U45.14 | length 23.1
  Top Layer w0.15: R258.2@99.8,77.953 103.453,77.953 v1(104.35,78.85)
  Bottom Layer w0.15: U45.14@102.95,78.848 101.802,78.848 101.35,79.3 101.35,82.7 101.95,83.3 107.7,83.3 108.875,84.475 U40.15@108.875,85.6 108.875,86.646 109.355,87.126 109.355,87.355 R171.1@109.55,87.55
  Bottom Layer w0.25: U45.14@102.969,78.849 v1@104.349,78.849
AIN_CTRL.AIN1_DRDY: M1.220 U48.6 | length 6.3
  Top Layer w0.15: v1(68.35,63) 68.4,63 69,63.6 M1.220@69,65.6
  Bottom Layer w0.15: U48.6@66,61.35 66.025,61.375 66.025,61.919 67.056,62.95 68.3,62.95 v1(68.35,63)
AIN_CTRL.AIN1_MODE: M1.216 U48.2 | length 7.9
  Top Layer w0.15: v1(66.4,63.65) 66.486,63.564 66.869,63.564 67.033,63.4 67.542,63.4 68,63.858 M1.216@68,65.6
  Bottom Layer w0.15: U48.2@64.4,61.5 64.4,62.133 64.225,62.308 64.225,63.225 64.831,63.831 66.097,63.831 66.278,63.65 v1(66.4,63.65)
AIN_CTRL.AIN2_DRDY: M1.222 U48.7 | length 6.6
  Top Layer w0.15: v1(69.15,62.85) 69.15,62.892 69.5,63.242 M1.222@69.5,65.6
  Bottom Layer w0.15: U48.7@66.4,61.35 66.425,61.375 66.425,61.895 67.005,62.475 68.775,62.475 v1(69.15,62.85)
AIN_CTRL.AIN2_MODE: M1.218 U48.3 | length 8
  Top Layer w0.15: v1(65.85,63.1) 67.667,63.1 68.5,63.933 M1.218@68.5,65.6
  Bottom Layer w0.15: U48.3@64.8,61.35 64.8,62.158 64.525,62.433 64.525,62.925 65,63.4 65.537,63.4 65.837,63.1 v1(65.85,63.1)
AVDD12: C39.2 C43.2 C46.2 C49.1 C51.2 C52.2 C54.1 C55.1 C56.2 C57.2 C59.1 C60.1 L7.2 U8.10 U8.16 U8.34 U8.46 U8.52 U8.53 | length 45.8
  Top Layer w0.25: C49.1@26.4,21.9 26.515,22.015 27.021,22.015 27.284,22.279 27.284,22.766 27.37,22.853 v1(27.37,22.947) ; C46.2@26.4,22.7 27.123,22.7 v1@27.237,22.814 ; v1(29.311,22.606) 29.311,22.701 29.575,22.964 29.575,23.225 C54.1@29.7,23.35 ; C56.2@30.9,29.65 30.911,29.639 v1(30.911,28.889) 30.978,28.956 31.256,28.956 31.575,29.275 31.575,29.525 C60.1@31.7,29.65 ; C57.2@32.85,29.65 32.962,29.538 32.962,29.238 v1(33.311,28.889) 33.649,29.226 33.649,29.549 C52.2@33.75,29.65 ; C59.1@35.173,21.15 35.168,21.155 34.645,21.155 34.45,21.35 v1(34.45,21.95) C55.1@35.173,21.95
  Top Layer w0.5: C51.2@29.311,21.85 v1(29.311,22.606)
  Top Layer w0.75: v1(27.5,34.95) L7.2@28.453,34.95
  L2-Signal w0.5: v1(27.37,22.947) 27.37,21.88 28.05,21.2 29.315,21.2 ; v1(27.5,34.95) 29.9,32.55 29.9,30.6 30.911,29.589 ; v1(29.311,22.606) 29.311,21.203 29.315,21.2 ; v1(30.911,28.889) 30.911,29.589 ; v1(33.311,28.889) 34.45,27.75 v1(34.45,21.95) 33.7,21.2 29.315,21.2 ; v1@33.358,28.869 32.627,29.6 30.923,29.6 30.911,29.589
  Bottom Layer w0.15: C43.2@25.4,22.547 U8.52@26.564,22.547 ; U8.53@26.564,22.947 v1(27.37,22.947) ; 27.176,22.547 27.287,22.658 ; U8.34@34.45,22.539 U8.34@34.459,22.547
  Bottom Layer w0.2: U8.52@26.564,22.547 27.176,22.547 ; U8.46@29.311,21.8 v1(29.311,22.606) ; v1(30.911,28.889) U8.10@30.911,29.695 ; v1(33.311,28.889) U8.16@33.311,29.695 ; v1(34.45,21.95) U8.34@34.45,22.539
  Bottom Layer w0.5: C39.2@26.65,35.166 27.257,35.166 27.473,34.95 v1(27.5,34.95)
AVDD33: C21.2 C26.2 C30.2 C33.2 C36.2 C40.2 C44.2 C47.2 C50.2 C53.2 L5.2 U8.4 U8.56 U8.61 U8.66 | length 16.7
  Top Layer w0.5: C21.2@20.231,27.181 21.081,27.181 v1(21.1,27.2) 21.103,27.197 21.98,27.197 L5.2@21.983,27.194
  L2-Signal w0.5: v1(21.1,27.2) 27.317,27.2 27.37,27.147 ; v1(27.37,24.147) v1(27.37,26.147) 27.37,27.147 ; v1(28.511,28.889) 28.492,28.869 28.119,28.869 27.397,28.147 v1(27.37,28.147) 27.37,27.147
  Bottom Layer w0.2: U8.56@26.564,24.147 v1(27.37,24.147) ; U8.61@26.564,26.147 v1(27.37,26.147) ; U8.66@26.564,28.147 v1(27.37,28.147) ; v1(28.511,28.889) U8.4@28.511,29.695
CAN1_H: J6.2 J19.2 U22.7 U24.2 | length 21.6
  Top Layer w0.15: 117.85,12.62 117.85,11.53 118.9,10.48 118.9,8.115 J19.2@120,7.015 118.4,5.415 118.4,4 118.715,3.685 119.381,3.685 119.741,4.045 U22.7@120.161,4.045
  Bottom Layer w0.15: U24.2@116.6,14.975 116.6,14.85 116.275,14.525 116.199,14.525 116.036,14.362 116.036,14.238 116.124,14.15 117.403,14.15 117.85,13.703 117.85,13.245 117.864,13.232 117.864,13.019 v1(117.95,12.933)
  Bottom Layer w0.25: U24.2@116.6,14.975 116.325,15.25 116.325,15.496 116.3,15.521 116.3,16.05 117.25,17 118.65,17 118.9,16.75 J6.2@118.9,15.5
CAN1_L: J6.4 J18.2 U22.6 U24.1 | length 22.7
  Top Layer w0.15: 117.3,12.637 117.3,11.302 118.35,10.252 118.35,7.965 J18.2@117.4,7.015 118.215,6.2 118.215,6.075 117.85,5.71 117.85,3.772 118.487,3.135 119.35,3.135 119.71,2.775 U22.6@120.161,2.775
  Bottom Layer w0.15: U24.1@115.199,14.85 115.3,14.85 115.625,14.525 115.625,14.424 115.7,14.349 115.7,13.898 115.923,13.675 117.1,13.675 117.3,13.475 117.3,13.263 117.286,13.249 117.286,13.036 v1(117.2,12.95)
  Bottom Layer w0.25: U24.1@115.3,15.1 115.7,15.5 115.7,16.1 117.15,17.55 118.65,17.55 118.9,17.8 J6.4@118.9,19
CAN1RX_1V8: M1.22 R227.2 R235.1 U20.3 | length 160.2
  Top Layer w0.15: M1.22@17.5,65.6 17.5,63.474 19.805,61.169 27.045,61.169 28.026,62.15 58.274,62.15 60.274,60.15 64.85,60.15 65.4,59.6 68.5,59.6 70.35,61.45 70.35,62.359 71.141,63.15 75.324,63.15 76.912,61.563 77.44,61.563 78.075,60.928 78.522,60.928 v1(78.6,60.85) ; v1(103.25,4.5) 103.31,4.56 104.25,4.56 105.281,5.591 105.281,6.191 105.615,6.525 U20.3@106.819,6.525
  Top Layer w0.25: v1(89.1,23.313) R227.2@89.1,24.05
  L1-Signal w0.15: v1(78.6,60.85) 78.661,60.911 78.661,61.375 80.688,63.403 86.474,63.403 89.102,60.775 89.102,56.825 94.631,51.297 94.631,47.653 93.878,46.9 93.878,38.55 95,37.427 95,36.473 94.353,35.826 94.353,29.703 89.1,24.45 v1(89.1,23.313)
  L2-Signal w0.15: v1(89.1,23.313) 89.115,23.298 89.115,22.885 90.809,21.191 90.809,18.141 103.25,5.7 v1(103.25,4.5)
  Bottom Layer w0.15: v1(103.25,4.5) 103.3,4.55 106.49,4.55 106.9,4.96 R235.1@108.6,4.96
CAN1TX_1V8: M1.20 R225.2 R234.1 U20.2 | length 157.8
  Top Layer w0.15: M1.20@17,65.6 17.005,65.595 17.005,64.588 17.025,64.567 17.025,63.525 19.681,60.869 27.169,60.869 28.15,61.85 58.15,61.85 60.2,59.8 64.776,59.8 65.326,59.25 68.6,59.25 70.65,61.3 70.65,62.235 71.265,62.85 75.2,62.85 76.787,61.263 76.987,61.263 v1(77.4,60.85) ; v1(102.95,7.71) 103.51,7.15 105.539,7.15 106.184,7.795 U20.2@106.819,7.795
  Top Layer w0.25: v1(90,23.313) R225.2@90,24.05
  L1-Signal w0.15: v1(77.4,60.85) 77.859,61.309 78.102,61.309 80.495,63.703 86.599,63.703 89.402,60.899 89.402,56.949 94.931,51.421 94.931,47.529 94.178,46.776 94.178,38.674 95.3,37.551 95.3,36.349 94.653,35.702 94.653,29.503 90,24.85 v1(90,23.313)
  L2-Signal w0.15: v1(90,23.313) 90,22.55 91.109,21.441 91.109,18.265 101.664,7.71 v1(102.95,7.71)
  Bottom Layer w0.15: v1(102.95,7.71) 103.51,7.15 108.59,7.15 R234.1@108.6,7.16
CAN2_H: J6.6 J21.2 U23.7 U25.1 | length 15.9
  Top Layer w0.15: U23.7@109.261,18.93 109.896,18.93 110.138,18.688 110.138,18.661 110.4,18.4 111.2,18.4 J21.2@111.7,18.9
  Bottom Layer w0.15: J21.2@111.7,18.9 112.802,18.9 113.577,18.125 114.6,18.125 115.975,19.5 115.975,21.247 116.175,21.447 116.175,21.7 116.55,22.075 U25.1@116.55,22.2
  Bottom Layer w0.25: U25.1@116.55,22.2 116.55,22.325 116.625,22.4 116.625,22.954 117.646,23.975 118.812,23.975 118.9,23.887 J6.6@118.9,22.5
CAN2_L: J6.8 J20.2 U23.6 U25.2 | length 16.3
  Top Layer w0.15: U23.6@109.261,17.66 109.896,17.66 110.336,18.1 112.35,18.1 113.15,18.9 J20.2@114.1,18.9
  Bottom Layer w0.15: J20.2@114.1,18.9 114.951,18.9 115.675,19.624 115.675,21.4 115.625,21.45 115.625,21.7 115.25,22.075 U25.2@115.25,22.2
  Bottom Layer w0.25: U25.2@115.25,22.2 115.25,22.325 115.639,22.714 115.639,23.104 115.785,23.25 116.214,23.25 116.575,23.611 117.489,24.525 118.812,24.525 118.9,24.613 J6.8@118.9,26
CAN2RX_1V8: M1.26 R228.2 R239.1 U21.3 | length 140.5
  Top Layer w0.15: M1.26@18.5,65.6 18.495,65.595 18.495,64.588 18.475,64.567 18.475,63.348 20.053,61.769 26.797,61.769 27.777,62.75 58.523,62.75 60.523,60.75 65.099,60.75 65.524,60.325 68.351,60.325 69.75,61.724 69.75,62.608 70.892,63.75 75.573,63.75 76.573,62.75 v1(78.05,62.75) ; U21.3@95.72,18.965 96.355,18.965 96.672,18.648 96.897,18.423 96.897,16.447 v1(96.45,16)
  Top Layer w0.25: v1(91.8,23.313) R228.2@91.8,24.05
  L1-Signal w0.15: v1(78.05,62.75) 79.603,64.303 86.847,64.303 90.002,61.148 90.002,57.359 96.475,50.886 96.475,47.875 94.778,46.178 94.778,39.047 94.778,38.922 95.9,37.8 95.9,36.1 95.253,35.453 95.253,27.103 91.852,23.702 91.852,23.365 v1(91.8,23.313)
  L2-Signal w0.15: v1(91.8,23.313) 91.814,23.298 91.814,22.884 92.073,22.625 92.267,22.625 92.575,22.317 92.575,21.852 92.225,21.502 92.225,18.909 92.959,18.175 93.167,18.175 95.342,16 v1(96.45,16)
  Bottom Layer w0.15: v1(96.45,16) 96.45,16.05 97.5,17.1 R239.1@97.5,17.4
CAN2TX_1V8: M1.24 R226.2 R238.1 U21.2 | length 137.1
  Top Layer w0.15: M1.24@18,65.6 18,63.399 19.929,61.469 26.921,61.469 27.901,62.45 58.399,62.45 60.399,60.45 64.974,60.45 65.399,60.025 68.475,60.025 70.05,61.6 70.05,62.483 71.017,63.45 75.449,63.45 76.999,61.9 v1(77.95,61.9) ; v1(92.05,22.1) 92.05,21.55 92.621,20.979 93.314,20.979 94.058,20.235 U21.2@95.72,20.235
  Top Layer w0.25: v1(90.9,23.313) R226.2@90.9,24.05
  L1-Signal w0.15: v1(77.95,61.9) 80.053,64.003 86.723,64.003 89.702,61.023 89.702,57.234 96.175,50.762 96.175,48.349 94.478,46.652 94.478,38.798 95.6,37.676 95.6,36.224 94.953,35.578 94.953,27.366 v1(90.9,23.313)
  L2-Signal w0.15: v1(90.9,23.313) 90.9,23.25 v1(92.05,22.1)
  Bottom Layer w0.15: v1(92.05,22.1) 95.954,22.1 96.232,21.823 97.477,21.823 R238.1@97.5,21.8
CLK_OUT: U26.18 X51.1 | length 5.8
  Bottom Layer w0.15: X51.1@44.15,29.15 44.075,29.075 44.075,23.975 44.225,23.825 U26.18@44.6,23.825
CTRL_RECOVERY_MICO#: M1.246 R218.1 | length 99.9
  Top Layer w0.15: M1.246@75.5,65.6 75.5,64.524 75.637,64.387 76.97,64.387 77.332,64.025 v1(77.35,64.025)
  L1-Signal w0.15: v1(43.85,36.55) 48.3,36.55 50.65,38.9 51.6,38.9 54.9,42.2 56.4,42.2 57.1,42.9 v1(57.1,42.95)
  L3-Signal w0.15: v1(16.35,16.35) 16.392,16.308 17.008,16.308 20.9,20.2 20.9,23.518 24.925,27.543 24.925,30.333 25.625,31.033 25.625,31.042 26.808,32.225 30.375,32.225 30.95,32.8 34.076,32.8 37.769,36.493 43.793,36.493 v1(43.85,36.55) ; v1(57.1,42.95) 57.65,42.95 59.3,44.6 59.3,48.2 59.55,48.45 62.55,48.45 64.35,50.25 66.2,50.25 67.25,51.3 67.25,58.696 67.279,58.725 ; 67.25,58.726 71.774,63.25 76.642,63.25 77.35,63.958 v1(77.35,64.025)
  Bottom Layer w0.15: R218.1@15.55,11.525 15.55,13.209 15.113,13.646 15.113,14.855 15.42,15.163 16.005,15.163 16.35,15.508 v1(16.35,16.35)
CTRL_RESET_MICO#: M1.260 R219.1 | length 106.2
  Top Layer w0.15: M1.260@79,65.6 79,64.5 79.35,64.15 80.642,64.15 82.15,62.642 82.15,60.641 v1(82.106,60.598)
  L1-Signal w0.15: v1(43.65,35.8) 44.45,35 48.45,35 49.75,36.3 49.75,37.5 50.85,38.6 51.75,38.6 55.05,41.9 56.976,41.9 59.85,44.774 v1(59.85,45.45)
  L3-Signal w0.15: v1(15.8,15.7) 17,15.7 21.2,19.9 21.2,23.394 25.225,27.419 25.225,30.208 25.925,30.908 25.925,30.917 26.858,31.85 30.658,31.85 31.108,32.3 34,32.3 37.85,36.15 43.3,36.15 v1(43.65,35.8) ; v1(59.85,45.45) 59.85,47.9 59.925,47.975 67.275,47.975 72.1,52.8 72.1,55.753 73.844,57.497 79.006,57.497 v1(82.106,60.598)
  Bottom Layer w0.15: R219.1@14.05,11.525 14.05,14.688 15.062,15.7 v1(15.8,15.7)
CTRL_RESET_MOCI#: M1.258 R8.1 R121.1 U26.43 | length 71.2
  Top Layer w0.15: M1.258@78.5,65.6 78.5,64.45 79.1,63.85 80.15,63.85 81.4,62.6 v1(81.4,60.85)
  L1-Signal w0.15: v1(55.25,25.2) 56.441,26.391 57.999,26.391 58.796,27.187 58.796,29.021 64.975,35.201 64.975,37.551 71.05,43.626 71.05,51.65 72.2,52.8 72.2,60.726 76.074,64.6 77.672,64.6 78,64.272 78,63.7 76.85,62.55 76.85,60.658 77.208,60.3 80.85,60.3 v1(81.4,60.85)
  Bottom Layer w0.15: U26.43@51.4,23.825 51.417,23.808 51.9,23.808 51.933,23.775 52.367,23.775 52.417,23.825 52.854,23.825 R121.1@52.875,23.803 54.147,23.803 R8.1@54.15,23.8 54.15,23.85 55.164,24.864 55.164,25.114 v1(55.25,25.2)
CTRL_WAKE1_MICO#: M1.252 R132.1 | length 10.7
  Top Layer w0.15: M1.252@77,65.6 77,66.7 77.6,67.3 80.026,67.3 81.8,69.074 81.8,70.9 82.6,71.7 R132.1@83.45,71.7
DIGI_1: M1.56 R197.2 U62.3 | length 89.7
  Top Layer w0.15: M1.56@26,65.6 26,67.05 27.65,68.7 27.65,74.05 34.3,80.7 v1(35.35,80.7) ; v1(91.6,97.5) 91.902,97.198 U62.3@92.795,97.198 94.15,97.198 R197.2@94.175,97.173
  L1-Signal w0.15: v1(35.35,80.7) 36.25,81.6 48.079,81.6 48.479,82 51.701,82 54.138,84.436 54.138,90.53 55.774,92.166 73.992,92.166 80.026,98.2 90.9,98.2 v1(91.6,97.5)
DIGI_2: M1.58 R198.2 U63.3 | length 84.5
  Top Layer w0.15: M1.58@26.5,65.6 26.5,66.974 28.1,68.574 28.1,73.935 34.34,80.175 35.623,80.175 v1(36.102,80.653) ; U63.3@85.865,97.15 87.292,97.15 R198.2@87.295,97.153 88.097,97.153 v1(88.1,97.15)
  L1-Signal w0.15: v1(36.102,80.653) 36.102,80.775 36.627,81.3 48.203,81.3 48.603,81.7 51.826,81.7 54.438,84.312 54.438,90.405 55.898,91.866 74.116,91.866 79.4,97.15 v1(88.1,97.15)
DIO1+: D27.2 D29.1 J5.12 | length 79.3
  Top Layer w0.15: D29.1@93.255,81.948 D29.1@93.275,81.969
  Top Layer w0.25: v1(93.45,86.1) 93.438,86.088 93.438,84.846 D27.2@93.525,84.758 D29.1@93.525,81.969
  L1-Signal w0.25: v1(93.45,86.1) 93.45,88.499 91.146,90.803 91.146,94.472 94.223,97.55 97.082,97.55 100.232,100.7 121.735,100.7 128.1,94.335 128.1,91.65 124.25,87.8 124.25,79.5 122.05,77.3 120.4,77.3 118.9,75.8 J5.12@118.9,75.5
DIO1-: D27.1 J5.11 U60.3 U62.2 | length 78.3
  Top Layer w0.25: U60.3@89.605,87.198 89.605,86.533 89.805,86.333 92.005,86.333 93.275,87.604 D27.1@93.275,88.788 ; v1(91.4,96) 92.795,94.605 92.795,90.348 93.255,89.888 D27.1@93.255,88.863
  L1-Signal w0.25: v1(91.4,96) 93.5,98.1 96.854,98.1 100.004,101.25 121.963,101.25 128.65,94.563 128.65,91.4 124.8,87.55 124.8,78.9 J5.11@121.4,75.5
DIO2+: D28.2 D30.1 J5.14 | length 76.3
  Top Layer w0.25: D30.1@86.575,81.925 D28.2@86.575,84.708 86.695,84.708 88.099,86.112 88.099,90.349 89.121,91.371 89.121,92.771 89.9,93.55 v1(91.9,93.55)
  L1-Signal w0.25: v1(91.9,93.55) 91.958,93.55 93.008,92.5 95.7,92.5 96.9,93.7 96.9,95.484 101.066,99.65 121.3,99.65 127.05,93.9 127.05,92.1 123.2,88.25 123.2,81.55 122.3,80.65 120.55,80.65 J5.14@118.9,79
DIO2-: D28.1 J5.13 U61.3 U63.2 | length 76.9
  Top Layer w0.25: U61.3@82.675,87.15 82.675,86.485 82.875,86.285 85.075,86.285 86.575,87.785 D28.1@86.575,88.738 86.575,89.59 85.865,90.3 U63.2@85.865,90.7 87.6,90.7 88.63,91.73 88.63,93.13 89.9,94.4 v1(91.9,94.4)
  L1-Signal w0.25: v1(91.9,94.4) 92.683,94.4 93.883,93.2 95.25,93.2 96.147,94.097 96.147,95.547 100.75,100.15 121.507,100.15 127.55,94.107 127.55,91.85 123.7,88 123.7,81.3 J5.13@121.4,79
DS2_N: C254.1 J16.U8 | length 7.3
  Top Layer w0.2: J16.U8@28.25,14.769 27.7,15.319 27.7,15.789 27.7,15.955 28.495,16.75 30.03,16.75 30.041,16.738 31.883,16.738 32.12,16.501 v1(32.2,16.501)
  Bottom Layer w0.2: C254.1@31.5,17 31.55,17 31.972,16.578 32.123,16.578 v1(32.2,16.501)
